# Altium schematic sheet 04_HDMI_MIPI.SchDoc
size A2; ApprovedBy: DNP; CheckedBy: DNP; Author: DNP; CompanyName: Google LLC; DrawnBy: DNP; Engineer: Bangfei/Michael/Leo; Organization: Google LLC; Address1: 1600 Amphitheatre Parkway; Address2: Mountain View, CA 94043; Address3: DNP; Address4: DNP; DocumentNumber: DNP; Revision: PVT; SheetNumber: 4; SheetTotal: 11; VersionControl_RevNumber: DNP; IsUserConfigurable: DNP
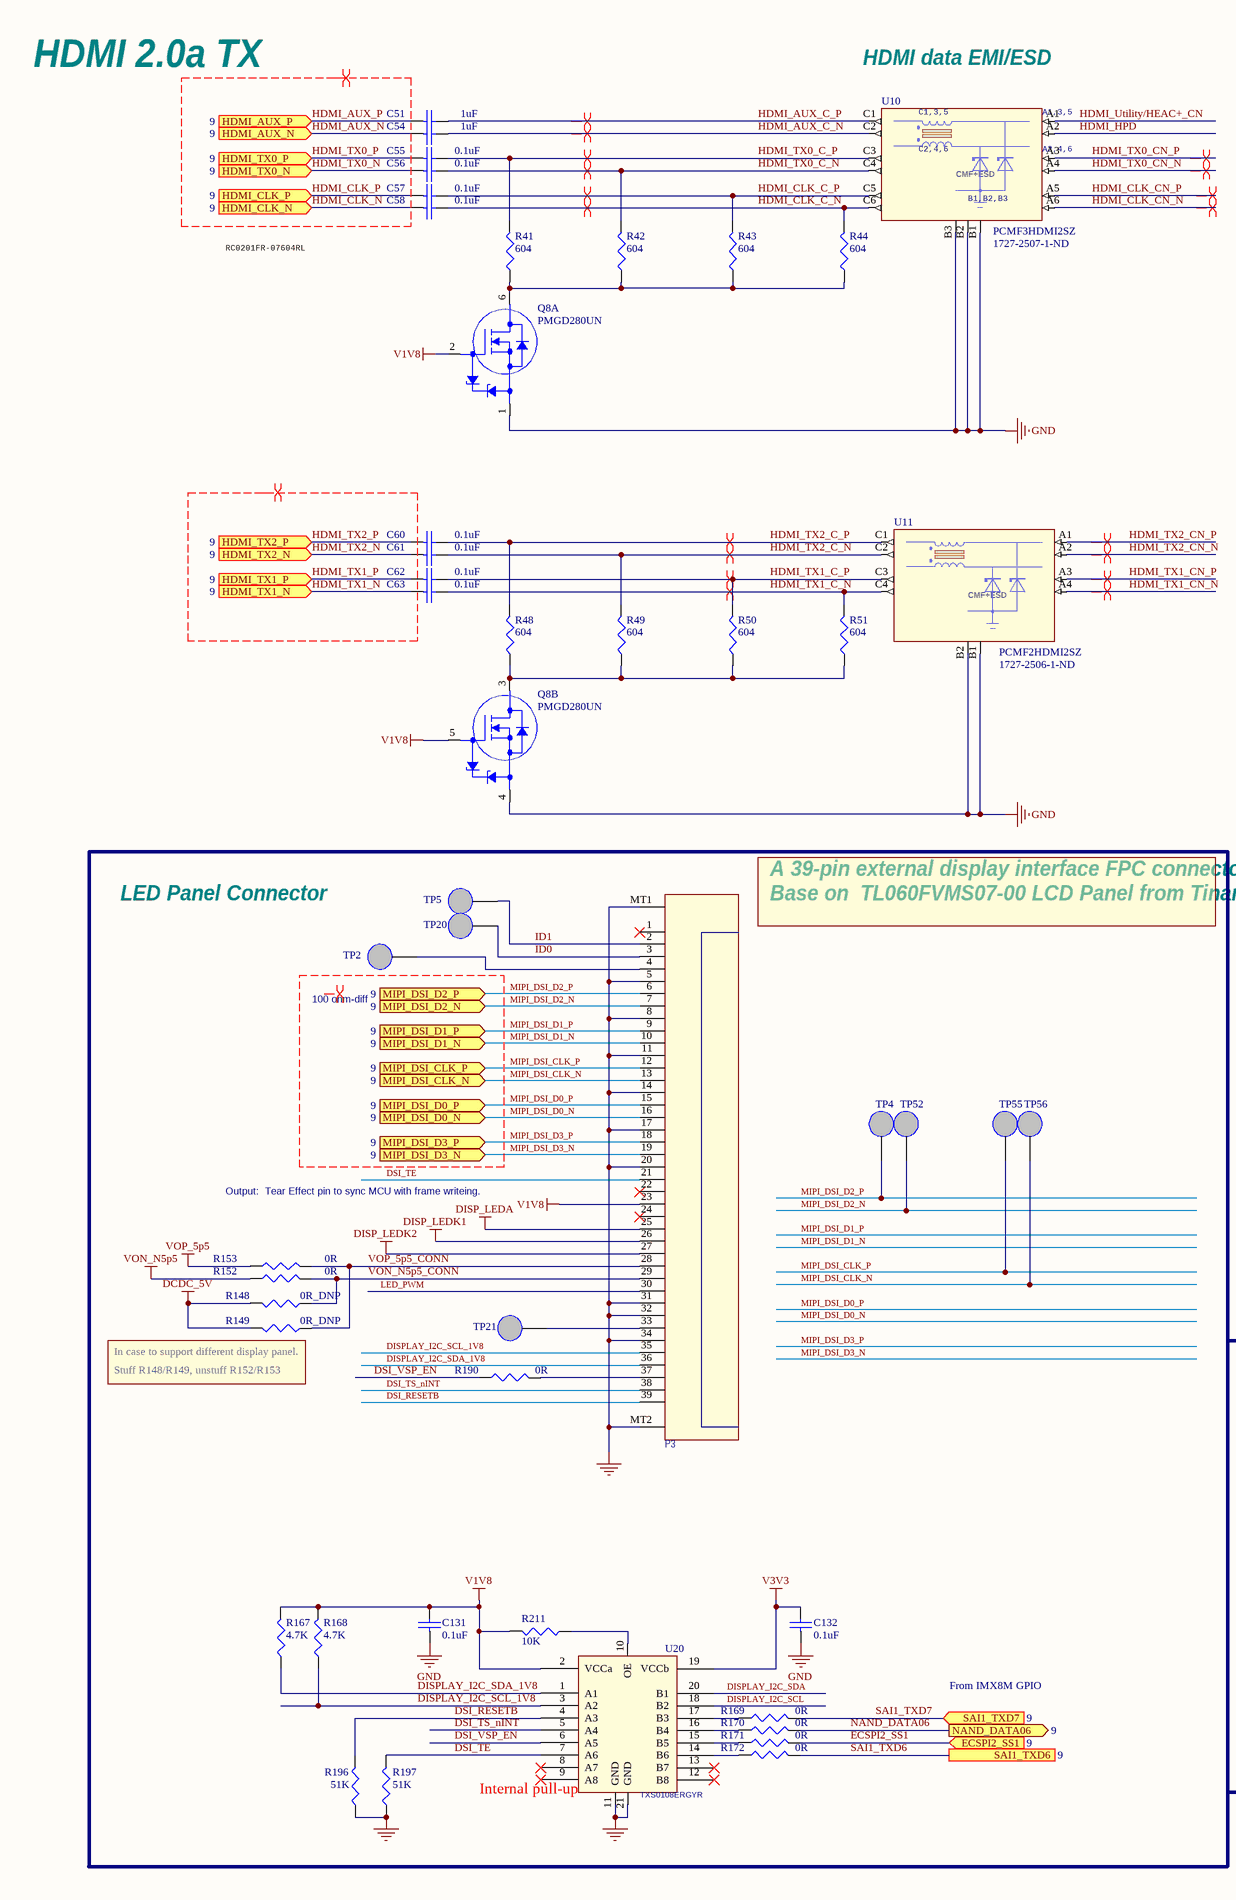
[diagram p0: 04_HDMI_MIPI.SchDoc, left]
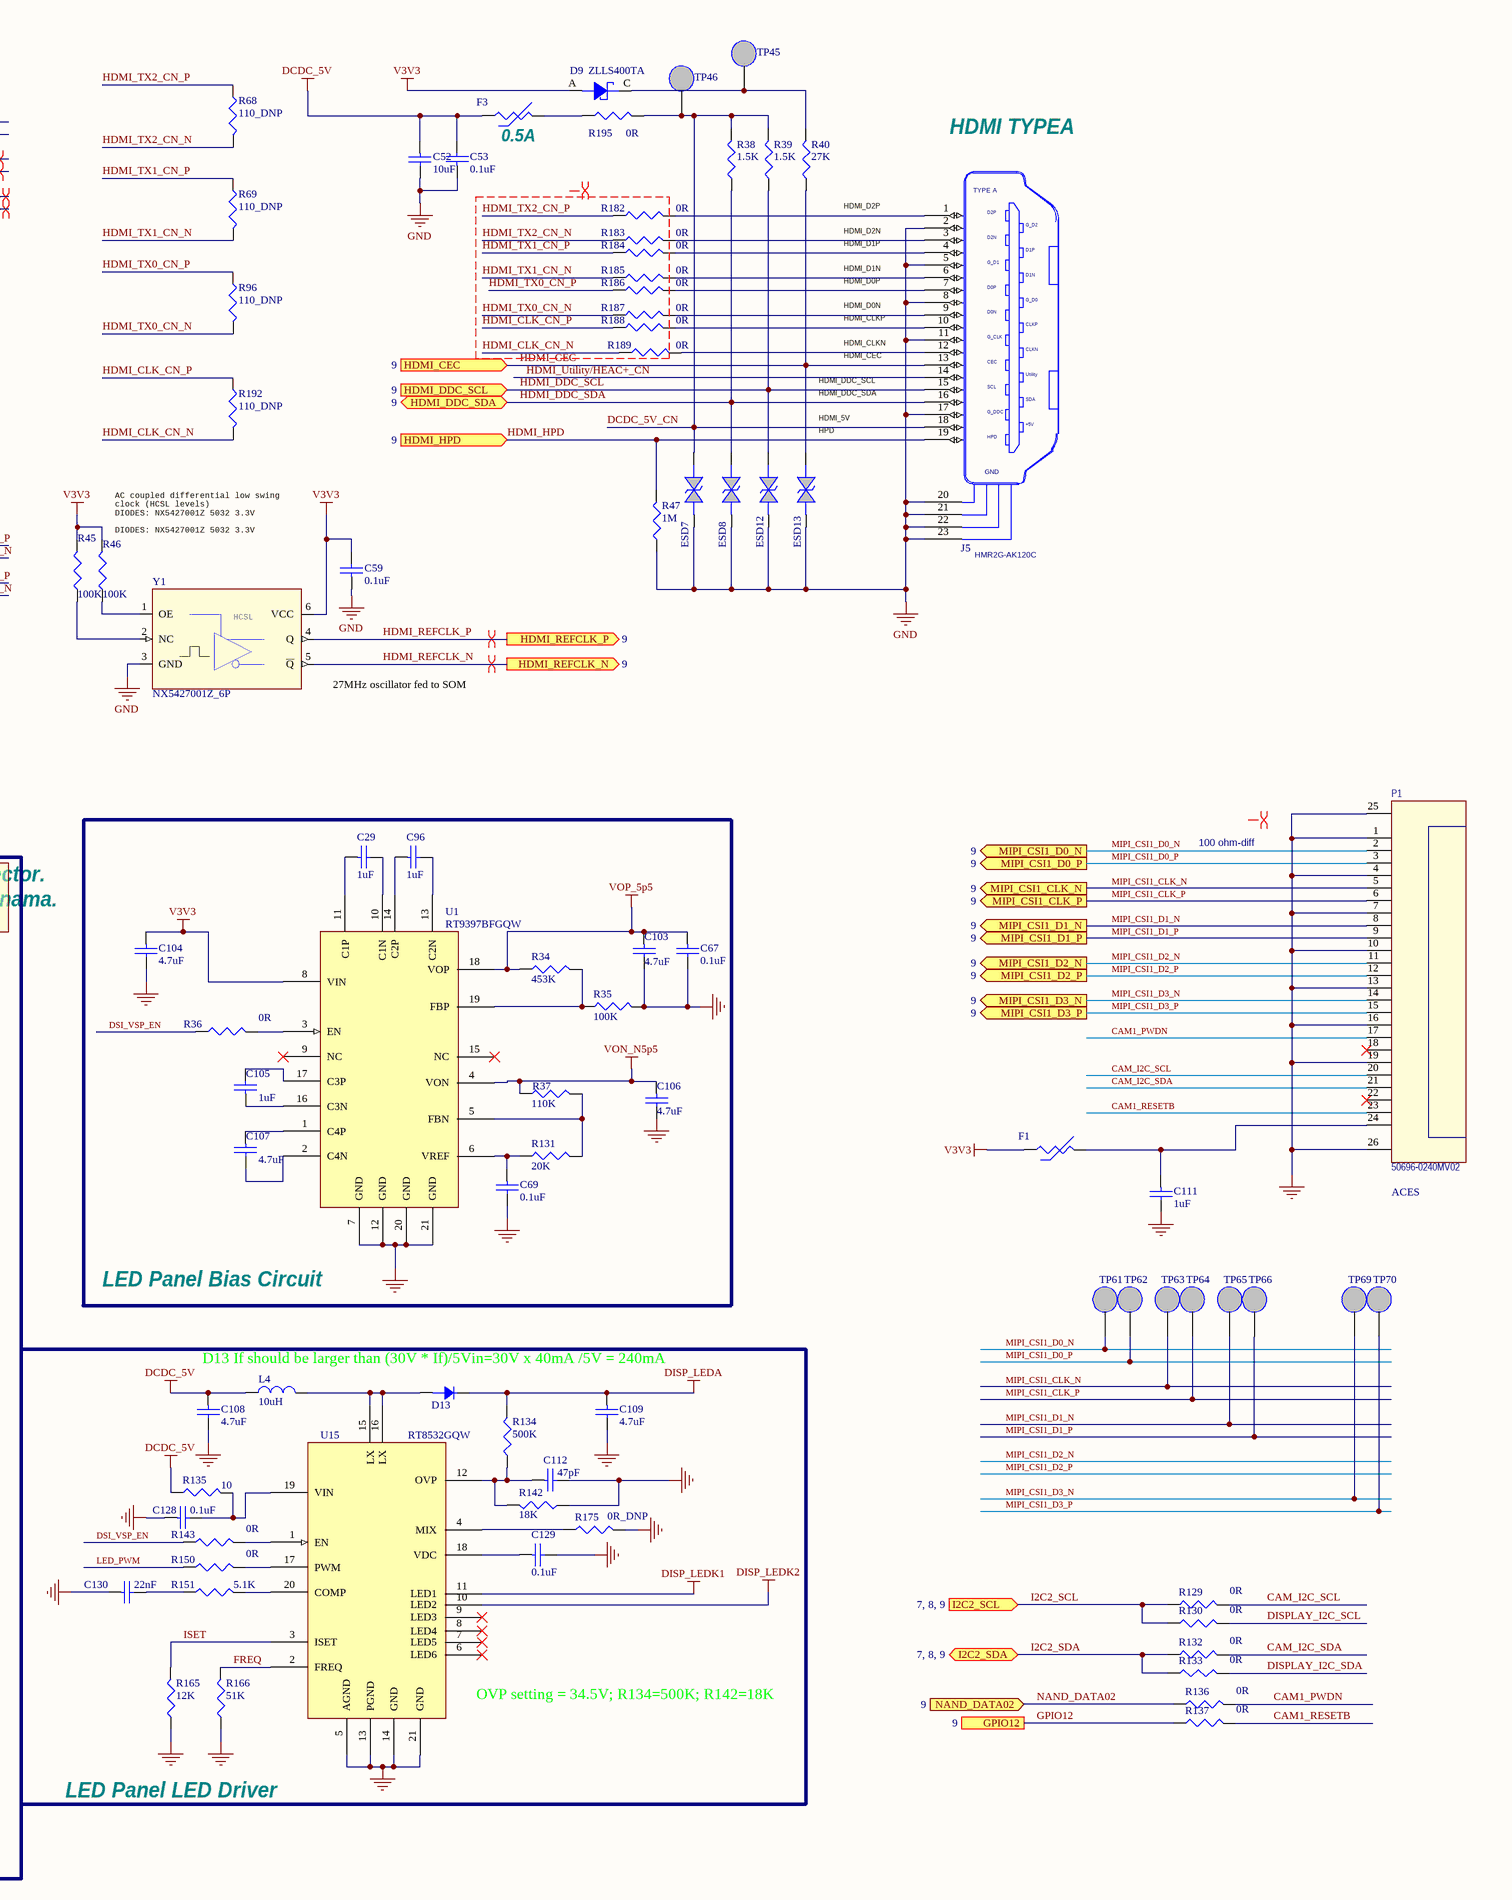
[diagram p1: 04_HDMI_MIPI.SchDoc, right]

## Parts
C29  value 1uF  [0201]  (hidden comment: 1uF/6.3V)
C51  value 1uF  [0402]  (hidden comment: 1uF/25V)
C52  value 10uF  [0402]  (hidden comment: 10uF/10V)
C53  value 0.1uF  [0201]  (hidden comment: 0.1uF/10V)
C54  value 1uF  [0402]  (hidden comment: 1uF/25V)
C55  value 0.1uF  [0201]  (hidden comment: 0.1uF/10V)
C56  value 0.1uF  [0201]  (hidden comment: 0.1uF/10V)
C57  value 0.1uF  [0201]  (hidden comment: 0.1uF/10V)
C58  value 0.1uF  [0201]  (hidden comment: 0.1uF/10V)
C59  value 0.1uF  [0201]  (hidden comment: 0.1uF/10V)
C60  value 0.1uF  [0201]  (hidden comment: 0.1uF/10V)
C61  value 0.1uF  [0201]  (hidden comment: 0.1uF/10V)
C62  value 0.1uF  [0201]  (hidden comment: 0.1uF/10V)
C63  value 0.1uF  [0201]  (hidden comment: 0.1uF/10V)
C67  value 0.1uF  [0201]  (hidden comment: 0.1uF/10V)
C69  value 0.1uF  [0201]  (hidden comment: 0.1uF/10V)
C96  value 1uF  [0201]  (hidden comment: 1uF/6.3V)
C103  value 4.7uF  [0402]  (hidden comment: 4.7uF/10V)
C104  value 4.7uF  [0402]  (hidden comment: 4.7uF/10V)
C105  value 1uF  [0201]  (hidden comment: 1uF/6.3V)
C106  value 4.7uF  [0402]  (hidden comment: 4.7uF/10V)
C107  value 4.7uF  [0402]  (hidden comment: 4.7uF/10V)
C108  value 4.7uF  [0402]  (hidden comment: 4.7uF/10V)
C109  value 4.7uF  [0402]  (hidden comment: 4.7uF/10V)
C111  value 1uF  [0201]  (hidden comment: 1uF/6.3V)
C112  value 47pF  [0201]  (hidden comment: 47pF/25V)
C128  value 0.1uF  [0201]  (hidden comment: 0.1uF/10V)
C129  value 0.1uF  [0201]  (hidden comment: 0.1uF/10V)
C130  value 22nF  [0201]  (hidden comment: 22nF/6.3V)
C131  value 0.1uF  [0201]  (hidden comment: 0.1uF/10V)
C132  value 0.1uF  [0201]  (hidden comment: 0.1uF/10V)
D9  ZLLS400TA  [SOD323]
D13  CUS10F30  [0805-Diode]  (value not drawn)
ESD7  3.5pF/5V  [0201]  (value not drawn)
ESD8  3.5pF/5V  [0201]  (value not drawn)
ESD12  3.5pF/5V  [0201]  (value not drawn)
ESD13  3.5pF/5V  [0201]  (value not drawn)
F1  PTC_FUSE_0805_0p5A  [0805]  (value not drawn)
F3  PTC_FUSE_0805_0p5A  [0805]  (value not drawn)
J5  HMR2G-AK120C  [HDMI19-HMR2G-AK120C]
L4  10uH  [AP3-00115]
P1  50696-0240MV02  QCI Supplier: ACES  [FPC24-0_5-14_18x4_71MM]
P3  FH26-39S-0.3SHW(05)  [FPC39-FH26W-39S-0_3SHW]  (value not drawn)
Q8  PMGD280UN  [SOT-363_0P65_SMT]  (parts A,B of 2)
R34  453K  [0201]
R35  100K  [0201]
R36  0R  [0201]
R37  110K  [0201]
R38  1.5K  [0201]
R39  1.5K  [0201]
R40  27K  [0201]
R41  604  [0201]
R42  604  [0201]
R43  604  [0201]
R44  604  [0201]
R45  100K  [0201]
R46  100K  [0201]
R47  1M  [0201]
R48  604  [0201]
R49  604  [0201]
R50  604  [0201]
R51  604  [0201]
R68  value 110_DNP  [0201]  (hidden comment: 110)
R69  value 110_DNP  [0201]  (hidden comment: 110)
R96  value 110_DNP  [0201]  (hidden comment: 110)
R129  0R  [0201]
R130  0R  [0201]
R131  20K  [0201]
R132  0R  [0201]
R133  0R  [0201]
R134  500K  [0201]
R135  10  [0201]
R136  0R  [0201]
R137  0R  [0201]
R142  18K  [0201]
R143  0R  [0201]
R148  0R_DNP  [0603]
R149  0R_DNP  [0603]
R150  0R  [0201]
R151  5.1K  [0201]
R152  0R  [0603]
R153  0R  [0603]
R165  12K  [0402]
R166  51K  [0201]
R167  4.7K  [0402]
R168  4.7K  [0402]
R169  0R  [0201]
R170  0R  [0201]
R171  0R  [0201]
R172  0R  [0201]
R175  0R_DNP  [0201]
R182  0R  [0201]
R183  0R  [0201]
R184  0R  [0201]
R185  0R  [0201]
R186  0R  [0201]
R187  0R  [0201]
R188  0R  [0201]
R189  0R  [0201]
R190  value 0R  [0201]  (hidden comment: 0R_DNP)
R192  value 110_DNP  [0201]  (hidden comment: 110)
R195  0R  [0603]
R196  51K  [0201]
R197  51K  [0201]
R211  10K  [0201]
TP2  TP NM  [TP_SMD]  (value not drawn)  (no BOM)
TP4  TP NM  [TP2040]  (value not drawn)  (no BOM)
TP5  TP NM  [TP_SMD]  (value not drawn)  (no BOM)
TP20  TP NM  [TP_SMD]  (value not drawn)  (no BOM)
TP21  TP NM  [TP_SMD]  (value not drawn)  (no BOM)
TP45  TP NM  [TP_SMD_L]  (value not drawn)  (no BOM)
TP46  TP NM  [TP_SMD_L]  (value not drawn)  (no BOM)
TP52  TP NM  [TP2040]  (value not drawn)  (no BOM)
TP55  TP NM  [TP2040]  (value not drawn)  (no BOM)
TP56  TP NM  [TP2040]  (value not drawn)  (no BOM)
TP61  TP NM  [TP2040]  (value not drawn)  (no BOM)
TP62  TP NM  [TP2040]  (value not drawn)  (no BOM)
TP63  TP NM  [TP2040]  (value not drawn)  (no BOM)
TP64  TP NM  [TP2040]  (value not drawn)  (no BOM)
TP65  TP NM  [TP2040]  (value not drawn)  (no BOM)
TP66  TP NM  [TP2040]  (value not drawn)  (no BOM)
TP69  TP NM  [TP2040]  (value not drawn)  (no BOM)
TP70  TP NM  [TP2040]  (value not drawn)  (no BOM)
U1  RT9397BFGQW  [WQFN20-0_4-3_1x3_1-H0_8MM-1]
U10  PCMF3HDMI2SZ  Supplier Part Number 1: 1727-2507-1-ND  [WLCSP15_0P4_2P42X1P22_SMDP]
U11  PCMF2HDMI2SZ  Supplier Part Number 1: 1727-2506-1-ND  [WLCSP10_0P4_1P2X1P6MM_SMDP]
U15  RT8532GQW  [WQFN20-0_4-3_1x3_1-H0_8MM-2]
U20  TXS0108ERGYR  [VQFN20-0_5-4_65X3_65MM-H1MM]
Y1  NX5427001Z_6P  [OSC6_1P27_5P2X3P4]

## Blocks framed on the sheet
LED Panel Bias Circuit: C29 C67 C69 C96 C103-C107 R34-R37 R131 U1
LED Panel LED Driver: C108 C109 C112 C128-C130 D13 L4 R134 R135 R142 R143 R150 R151 R165 R166 R175 U15

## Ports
ECSPI2_SS1 (in, see 9), GPIO12 (see 9), HDMI_AUX_N (in, see 9), HDMI_AUX_P (in, see 9), HDMI_CEC (in, see 9), HDMI_CLK_N (in, see 9), HDMI_CLK_P (in, see 9), HDMI_DDC_SCL (in, see 9), HDMI_DDC_SDA (bidir, see 9), HDMI_HPD (in, see 9), HDMI_REFCLK_N (out, see 9), HDMI_REFCLK_P (out, see 9), HDMI_TX0_N (in, see 9), HDMI_TX0_P (in, see 9), HDMI_TX1_N (in, see 9), HDMI_TX1_P (in, see 9), HDMI_TX2_N (in, see 9), HDMI_TX2_P (in, see 9), I2C2_SCL (in, see 7, 8, 9), I2C2_SDA (bidir, see 7, 8, 9), MIPI_CSI1_CLK_N (out, see 9), MIPI_CSI1_CLK_P (out, see 9), MIPI_CSI1_D0_N (out, see 9), MIPI_CSI1_D0_P (out, see 9), MIPI_CSI1_D1_N (out, see 9), MIPI_CSI1_D1_P (out, see 9), MIPI_CSI1_D2_N (out, see 9), MIPI_CSI1_D2_P (out, see 9), MIPI_CSI1_D3_N (out, see 9), MIPI_CSI1_D3_P (out, see 9), MIPI_DSI_CLK_N (in, see 9), MIPI_DSI_CLK_P (in, see 9), MIPI_DSI_D0_N (in, see 9), MIPI_DSI_D0_P (in, see 9), MIPI_DSI_D1_N (in, see 9), MIPI_DSI_D1_P (in, see 9), MIPI_DSI_D2_N (in, see 9), MIPI_DSI_D2_P (in, see 9), MIPI_DSI_D3_N (in, see 9), MIPI_DSI_D3_P (in, see 9), NAND_DATA02 (in, see 9), NAND_DATA06 (out, see 9), SAI1_TXD6 (see 9), SAI1_TXD7 (in, see 9)

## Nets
DCDC_5V: C52.1 C53.2 C108.1 F3.1 L4.1 R135.1 R148.2 R149.2
DISP_LEDA: C109.1 D13.K P3.25 R134.2
DISP_LEDK1: P3.26 U15.11(LED1)
DISP_LEDK2: P3.27 U15.10(LED2)
GND: C52.2 C53.1 C59.1 C67.2 C69.2 C103.2 C104.2 C106.2 C108.2 C109.2 C111.2 C112.2 C128.1 C129.2 C130.1 C131.1 C132.1 ESD7.1 ESD8.1 ESD12.1 ESD13.1 J5.2(D2GND) J5.5(D1GND) J5.8(D0GND) J5.11(CKGND) J5.17(DDCGND) J5.20(GND1) J5.21(GND2) J5.22(GND3) J5.23(GND4) P1.1 P1.4 P1.7 P1.10 P1.13 P1.16 P1.19 P1.25 P1.26 P3.5 P3.8 P3.11 P3.14 P3.17 P3.20 P3.31 P3.32 P3.34 P3.MT1 P3.MT2 Q8.1(S1) Q8.4(S2) R35.2 R47.1 R142.1 R165.1 R166.1 R175.2 R196.1 R197.1 U1.7(GND) U1.12(GND) U1.20(GND) U1.21(GND) U10.B1(GND_CH1) U10.B2(GND_CH2) U10.B3(GND_CH3) U11.B1(GND_CH1) U11.B2(GND_CH2) U15.5(AGND) U15.13(PGND) U15.14(GND) U15.21(GND) U20.11(GND) U20.21(GND) Y1.3(GND)
V1V8: C131.2 P3.23 Q8.2(G1) Q8.5(G2) R167.2 R168.2 R211.2 U20.2(VCCa)
V3V3: C59.2 C104.1 C132.2 D9.A F1.1 R45.2 R46.2 U1.8(VIN) U20.19(VCCb) Y1.6(VCC)
VON_N5p5: C106.1 R37.1 R152.1 U1.4(VON)
VOP_5p5: C67.1 C103.1 R34.1 R153.1 U1.18(VOP)
CAM1_PWDN: P1.17 R136.2
CAM1_RESETB: P1.23 R137.2
CAM_I2C_SCL: P1.20 R129.2
CAM_I2C_SDA: P1.21 R132.2
DCDC_5V_CN: ESD7.2 J5.18(+5V) R38.2 R39.2 R195.2 TP46.1
DISPLAY_I2C_SCL: R130.2 U20.18(B2)
DISPLAY_I2C_SCL_1V8: P3.35 R168.1 U20.3(A2)
DISPLAY_I2C_SDA: R133.2 U20.20(B1)
DISPLAY_I2C_SDA_1V8: P3.36 R167.1 U20.1(A1)
DSI_RESETB: P3.39 R196.2 U20.4(A3)
DSI_TE: P3.21 R197.2 U20.7(A6)
DSI_TS_nINT: P3.38 U20.5(A4)
DSI_VSP_EN: R36.1 R143.1 R190.1 U20.6(A5)
ECSPI2_SS1: R171.2 ; port ECSPI2_SS1
FREQ: R166.2 U15.2(FREQ)
GPIO12: R137.1 ; port GPIO12
HDMI_AUX_C_N: C54.2 U10.C2(CH1_OUT-)
HDMI_AUX_C_P: C51.2 U10.C1(CH1_OUT+)
HDMI_AUX_N: C54.1 ; port HDMI_AUX_N
HDMI_AUX_P: C51.1 ; port HDMI_AUX_P
HDMI_CEC: ESD13.2 J5.13(CEC) R40.1 ; port HDMI_CEC
HDMI_CLK_C_N: C58.2 R44.2 U10.C6(CH3_OUT-)
HDMI_CLK_C_P: C57.2 R43.2 U10.C5(CH3_OUT+)
HDMI_CLK_CN_N: R189.1 R192.2 U10.A6(CH3_IN-)
HDMI_CLK_CN_P: R188.1 R192.1 U10.A5(CH3_IN+)
HDMI_CLK_N: C58.1 ; port HDMI_CLK_N
HDMI_CLK_P: C57.1 ; port HDMI_CLK_P
HDMI_DDC_SCL: ESD12.2 J5.15(SCL) R39.1 ; port HDMI_DDC_SCL
HDMI_DDC_SDA: ESD8.2 J5.16(SDA) R38.1 ; port HDMI_DDC_SDA
HDMI_HPD: J5.19(HPD) R47.2 U10.A2(CH1_IN-) ; port HDMI_HPD
HDMI_REFCLK_N: Y1.5(~{Q}) ; port HDMI_REFCLK_N
HDMI_REFCLK_P: Y1.4(Q) ; port HDMI_REFCLK_P
HDMI_TX0_C_N: C56.2 R42.2 U10.C4(CH2_OUT-)
HDMI_TX0_C_P: C55.2 R41.2 U10.C3(CH2_OUT+)
HDMI_TX0_CN_N: R96.2 R187.1 U10.A4(CH2_IN-)
HDMI_TX0_CN_P: R96.1 R186.1 U10.A3(CH2_IN+)
HDMI_TX0_N: C56.1 ; port HDMI_TX0_N
HDMI_TX0_P: C55.1 ; port HDMI_TX0_P
HDMI_TX1_C_N: C63.2 R51.2 U11.C4(CH2_OUT-)
HDMI_TX1_C_P: C62.2 R50.2 U11.C3(CH2_OUT+)
HDMI_TX1_CN_N: R69.2 R185.1 U11.A4(CH2_IN-)
HDMI_TX1_CN_P: R69.1 R184.1 U11.A3(CH2_IN+)
HDMI_TX1_N: C63.1 ; port HDMI_TX1_N
HDMI_TX1_P: C62.1 ; port HDMI_TX1_P
HDMI_TX2_C_N: C61.2 R49.2 U11.C2(CH1_OUT-)
HDMI_TX2_C_P: C60.2 R48.2 U11.C1(CH1_OUT+)
HDMI_TX2_CN_N: R68.2 R183.1 U11.A2(CH1_IN-)
HDMI_TX2_CN_P: R68.1 R182.1 U11.A1(CH1_IN+)
HDMI_TX2_N: C61.1 ; port HDMI_TX2_N
HDMI_TX2_P: C60.1 ; port HDMI_TX2_P
HDMI_Utility/HEAC+_CN: J5.14(Utility) U10.A1(CH1_IN+)
I2C2_SCL: R129.1 R130.1 ; port I2C2_SCL
I2C2_SDA: R132.1 R133.1 ; port I2C2_SDA
ID0: P3.3 TP20.1
ID1: P3.2 TP5.1
ISET: R165.2 U15.3(ISET)
LED_PWM: P3.30 R150.1
MIPI_CSI1_CLK_N: P1.5 TP63.1 ; port MIPI_CSI1_CLK_N
MIPI_CSI1_CLK_P: P1.6 TP64.1 ; port MIPI_CSI1_CLK_P
MIPI_CSI1_D0_N: P1.2 TP61.1 ; port MIPI_CSI1_D0_N
MIPI_CSI1_D0_P: P1.3 TP62.1 ; port MIPI_CSI1_D0_P
MIPI_CSI1_D1_N: P1.8 TP65.1 ; port MIPI_CSI1_D1_N
MIPI_CSI1_D1_P: P1.9 TP66.1 ; port MIPI_CSI1_D1_P
MIPI_CSI1_D2_N: P1.11 ; port MIPI_CSI1_D2_N
MIPI_CSI1_D2_P: P1.12 ; port MIPI_CSI1_D2_P
MIPI_CSI1_D3_N: P1.14 TP69.1 ; port MIPI_CSI1_D3_N
MIPI_CSI1_D3_P: P1.15 TP70.1 ; port MIPI_CSI1_D3_P
MIPI_DSI_CLK_N: P3.13 TP56.1 ; port MIPI_DSI_CLK_N
MIPI_DSI_CLK_P: P3.12 TP55.1 ; port MIPI_DSI_CLK_P
MIPI_DSI_D0_N: P3.16 ; port MIPI_DSI_D0_N
MIPI_DSI_D0_P: P3.15 ; port MIPI_DSI_D0_P
MIPI_DSI_D1_N: P3.10 ; port MIPI_DSI_D1_N
MIPI_DSI_D1_P: P3.9 ; port MIPI_DSI_D1_P
MIPI_DSI_D2_N: P3.7 TP52.1 ; port MIPI_DSI_D2_N
MIPI_DSI_D2_P: P3.6 TP4.1 ; port MIPI_DSI_D2_P
MIPI_DSI_D3_N: P3.19 ; port MIPI_DSI_D3_N
MIPI_DSI_D3_P: P3.18 ; port MIPI_DSI_D3_P
NAND_DATA02: R136.1 ; port NAND_DATA02
NAND_DATA06: R170.2 ; port NAND_DATA06
SAI1_TXD6: R172.2 ; port SAI1_TXD6
SAI1_TXD7: R169.2 ; port SAI1_TXD7
VON_N5p5_CONN: P3.29 R148.1 R152.2
VOP_5p5_CONN: P3.28 R149.1 R153.2
NetC29_1: C29.1 U1.11(C1P)
NetC29_2: C29.2 U1.10(C1N)
NetC69_1: C69.1 R131.1 U1.6(VREF)
NetC96_1: C96.1 U1.14(C2P)
NetC96_2: C96.2 U1.13(C2N)
NetC105_1: C105.1 U1.16(C3N)
NetC105_2: C105.2 U1.17(C3P)
NetC107_1: C107.1 U1.1(C4P)
NetC107_2: C107.2 U1.2(C4N)
NetC111_1: C111.1 F1.2 P1.24
NetC112_1: C112.1 R134.1 R142.2 U15.12(OVP)
NetC128_2: C128.2 R135.2 U15.19(VIN)
NetC129_1: C129.1 U15.18(VDC)
NetC130_2: C130.2 R151.1
NetD9_C: D9.C R40.2 TP45.1
NetD13_A: D13.A L4.2 U15.15(LX) U15.16(LX)
NetF3_2: F3.2 R195.1
NetJ5_1: J5.1(D2+) R182.2
NetJ5_3: J5.3(D2-) R183.2
NetJ5_4: J5.4(D1+) R184.2
NetJ5_6: J5.6(D1-) R185.2
NetJ5_7: J5.7(D0+) R186.2
NetJ5_9: J5.9(D0-) R187.2
NetJ5_10: J5.10(CK+) R188.2
NetJ5_12: J5.12(CK-) R189.2
NetP3_4: P3.4 TP2.1
NetP3_33: P3.33 TP21.1
NetP3_37: P3.37 R190.2
NetQ8_3: Q8.3(D2) R48.1 R49.1 R50.1 R51.1
NetQ8_6: Q8.6(D1) R41.1 R42.1 R43.1 R44.1
NetR34_2: R34.2 R35.1 U1.19(FBP)
NetR36_2: R36.2 U1.3(EN)
NetR37_2: R37.2 R131.2 U1.5(FBN)
NetR45_1: R45.1 Y1.2(NC)
NetR46_1: R46.1 Y1.1(OE)
NetR143_2: R143.2 U15.1(EN)
NetR150_2: R150.2 U15.17(PWM)
NetR151_2: R151.2 U15.20(COMP)
NetR169_1: R169.1 U20.17(B3)
NetR170_1: R170.1 U20.16(B4)
NetR171_1: R171.1 U20.15(B5)
NetR172_1: R172.1 U20.14(B6)
NetR175_1: R175.1 U15.4(MIX)
NetR211_1: R211.1 U20.10(OE)

Not connected (* = marked no-connect by the designer): P1 18* 22*; P3 1* 22* 24*; U1 9(NC)* 15(NC)*; U15 6(LED6)* 7(LED5)* 8(LED4)* 9(LED3)*; U20 8(A7)* 9(A8)* 12(B8)* 13(B7)*

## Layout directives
differential pair: (no net found under the mark), HDMI_AUX_C_N, HDMI_AUX_C_P, HDMI_AUX_N, HDMI_AUX_P, HDMI_CLK_C_N, HDMI_CLK_C_P, HDMI_CLK_CN_N, HDMI_CLK_CN_P, HDMI_CLK_N, HDMI_CLK_P, HDMI_REFCLK_N, HDMI_REFCLK_P, HDMI_TX0_C_N, HDMI_TX0_C_P, HDMI_TX0_CN_N, HDMI_TX0_CN_P, HDMI_TX0_N, HDMI_TX0_P, HDMI_TX1_C_N, HDMI_TX1_C_P, HDMI_TX1_CN_N, HDMI_TX1_CN_P, HDMI_TX1_N, HDMI_TX1_P, HDMI_TX2_C_N, HDMI_TX2_C_P, HDMI_TX2_CN_N, HDMI_TX2_CN_P, HDMI_TX2_N, HDMI_TX2_P

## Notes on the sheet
- HDMI 2.0a TX
- HDMI data EMI/ESD
- (near F3) 0.5A
- HDMI TYPEA
- (near R40) HDMI_D2P
- HDMI_D2N
- RC0201FR-07604RL
- HDMI_D1P
- HDMI_D1N
- HDMI_D0P
- HDMI_D0N
- HDMI_CLKP
- HDMI_CLKN
- HDMI_CEC
- HDMI_DDC_SCL
- HDMI_DDC_SDA
- HDMI_5V
- (near ESD13) HPD
- (near R46) DIODES: NX5427001Z 5032 3.3V
- AC coupled differential low swing
  clock (HCSL levels)
  DIODES: NX5427001Z 5032 3.3V
- (near Y1) 27MHz oscillator fed to SOM
- 100 ohm-diff
- LED Panel Connector
- A 39-pin external display interface FPC connector.
- Base on  TL060FVMS07-00 LCD Panel from Tinama.
- (near TP2) 100 ohm-diff
- Output:  Tear Effect pin to sync MCU with frame writeing.
- (near R149) In case to support different display panel.
- (near R149) Stuff R148/R149, unstuff R152/R153
- D13 If should be larger than (30V * If)/5Vin=30V x 40mA /5V = 240mA
- From IMX8M GPIO
- (near U15) OVP setting = 34.5V; R134=500K; R142=18K
- (near U20) Internal pull-up

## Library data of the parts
C29 C96 C105 = CAP_0201_1.0uF: CAP CER 1UF 6.3V 20% X5R 0201; MPN: C0603X5R0J105M030BC; QCI MPN: GRM033R60J105M; QPN: CH5101M9E02; QPN Description: CAP CHIP 1UF 6.3V(+-20%,X5R,0201); Function Code: LCD
C51 C54 = CAP_0402_1.0uF_25V: CAP CER 1.0UF 25V 10% X5R 0402; MPN: TMK105BJ105MV-F; QCI MPN: GRM155R61E105K; QPN: CH5104K9B01; QPN Description: CAP CHIP 1UF 25V(+-10%,X5R,0402); Function Code: HMI
C52 = CAP_0402_10uF: CAP CER 10UF 10V 20% X5R 0402; MPN: CL05A106MP5NUNC; QCI MPN: GRM155R61A106M; QPN: CH6102M9B00; QPN Description: CAP CHIP 10U 10V (+-20%, X5R, 0402)'; Function Code: HMI
C53 C55-C58 C60-C63 = CAP_0201_0.1uF: CAP CER 0.1UF 10V 10% X5R 0201; MPN: C0603X5R1A104K030BC; QCI MPN: GRM033R61A104K; QPN: CH4102K9E00; QPN Description: CAP CHIP 0.1U 10V(+-10%,X5R,0201); Function Code: HMI
C59 = CAP_0201_0.1uF: CAP CER 0.1UF 10V 10% X5R 0201; MPN: C0603X5R1A104K030BC; QCI MPN: GRM033R61A104K; QPN: CH4102K9E00; QPN Description: CAP CHIP 0.1U 10V(+-10%,X5R,0201); Function Code: SOC
C67 C69 C128 C129 C131 C132 = CAP_0201_0.1uF: CAP CER 0.1UF 10V 10% X5R 0201; MPN: C0603X5R1A104K030BC; QCI MPN: GRM033R61A104K; QPN: CH4102K9E00; QPN Description: CAP CHIP 0.1U 10V(+-10%,X5R,0201); Function Code: LCD
C103 C104 C106-C109 = CAP_0402_4.7uF: CAP CER 4.7UF 10V 20% X5R 0402; MPN: C1005X5R1A475M050BC; QCI MPN: GRM155R61A475M; QPN: CH5472M9B01; QPN Description: CAP CHIP 4.7U 10V(+-20%,X5R,0402); Function Code: LCD
C111 = CAP_0201_1.0uF: CAP CER 1UF 6.3V 20% X5R 0201; MPN: C0603X5R0J105M030BC; QCI MPN: GRM033R60J105M; QPN: CH5101M9E02; QPN Description: CAP CHIP 1UF 6.3V(+-20%,X5R,0201); Function Code: CAM
C112 = CAP_0201_47pF: CAP CER 47PF 25V 0201; MPN: GRM0335C1E470FA01D; QCI MPN: GRM0335C1E470J; QPN: CH0474J0E09; QPN Description: CAP CHIP 47P 25V(+-5%,COG,0201); Function Code: LCD
C130 = CAP_0201_22nF: CAP CER 0.022UF 6.3V 10% X5R 0201; MPN: CC0201KRX5R5BB223; QCI MPN: GRM033R60J223K; QPN: CH3221K9E00; QPN Description: CAP CHIP 0.022U 6.3V(+-10%,X5R,0201); Function Code: LCD
D9 = DIODE_SCHTKY: DIODE SCHOTTKY 40V 520MA SOD323; Function Code: HMI; QPN: BCS400TA000; QPN Description: DIODE SCHOTTKY ZLLS400TA(20V,1A)
D13 = Diode_Schottky_0805: DIODE SCHOTTKY 20V 1A 0805; Function Code: LCD; QPN: BC0CUS10000; QPN Description: DIODE SMD SCHOTTKY  CUS10F30(30V,1A)
ESD7 ESD8 ESD12 ESD13 = DIODE BI-DIR TRIG: DIODE TVS 15kV 10V 50A 8pF SMT RoHS; MPN: DESD5V0V1BCSP-7; QPN: BC5V0V1BZ02; QPN Description: DIODE ESD SMD DESD5V0V1BCSP-7 6V,DSN0603; Function Code: HMI
F1 = PTC_FUSE_0805_0p5A: PTC FUSE 0.5A 0805; QCI MPN: SMD0805P050TF; QPN: DK050TPU004; QPN Description: FUSE SMD 0.5A 6V POLY(SMD0805P050TF); Function Code: CAM
F3 = PTC_FUSE_0805_0p5A: PTC FUSE 0.5A 0805; QCI MPN: SMD0805P050TF; QPN: DK050TPU004; QPN Description: FUSE SMD 0.5A 6V POLY(SMD0805P050TF); Function Code: HMI
J5 = CONN_HDMI_TYPEA_ACON_HMR2G-AK120C: CONN RCPT 19POS HDMI DIP WO FLANGE; Function Code: HMI; QPN: DFHD19MR637; QPN Description: CONN DIP HDMI 19P 2R MR(P0.5,H5.55)
L4 = INDUCTOR_LQH3NPN100MJ0: FIXED IND 10UH 710MA 300 MOHM; MPN: LQH3NPN100MJRL; Function Code: LCD; QPN: CV01009MN01; QPN Description: IND CHIP 10UH 0.81A +-20% LQH3NPN100MJRL
P1 = CONN_ACES_50696-0240MV02: Connector,FP, .5mm pitch, 24-pin, R/A,  SMT; QCI MPN: 50696-0240M-V02; Function Code: CAM; QPN: DFFC24FR095; QPN Description: CONN SMD FPC 24P 1R FR(P0.5,H1.0)
P3 = CONN_FH26-39S-0.3SHW(0.5): Connector,FP, .30mm pitch, 39-pin, R/A,  SMT; QPN: DFFC39FR004; QPN Description: CONN SMD FPC 39P 2R FR(P0.6,H0.1); Function Code: LCD
Q8 = TRAN_DUAL_NMOS_BSS138: TRANS MOSFET (20V,0.87A,0.4W) SOT363; QPN: BC5V0V1BZ02; QPN Description: DIODE ESD SMD DESD5V0V1BCSP-7 6V,DSN0603; Function Code: HMI
R34 = R_0201_453K: RES SMD 453K OHM JUMPER 1/20W  0201; MPN: ERJ-1GEF4533C; QCI MPN: RM02FTN4533; QPN: CS44531FE00; QPN Description: RES CHIP 453K 1/20W +-1%(0201); Function Code: LCD
R35 = R_0201_100K: RES SMD 100K OHM JUMPER 1/20W  0201; MPN: ERJ-1GEF1003C; QCI MPN: RC0201FR-07100KL; QPN: TS41001FE04; QPN Description: RES CHIP 100K 1/20W +-1%(0201)EMS-SEL; Function Code: LCD
R36 R143 R150 R169-R172 = R_0201_0: RES SMD 0.0OHM JUMPER 1/20W 0201; MPN: ERJ-1GN0R00C; QCI MPN: RC0201JR-130RL; QPN: CS00001JE18; QPN Description: RES CHIP 0(1/20W,+-5%,0201); Function Code: LCD
R37 = R_0201_110K: RES SMD 110K OHM  +/-1% 1/20W  0201; MPN: ERJ-1GNF1103C; QCI MPN: RC0201FR-07110KL; QPN: CS41101FE00; QPN Description: RES CHIP 110K 1/20W 1% (0201); Function Code: LCD
R38 R39 = R_0201_1.5K: RES SMD 1.5K OHM JUMPER 1/20W  0201; MPN: ERJ-1GEJ6152C; QCI MPN: RC0201FR-071K5L; QPN: CS21501FE01; QPN Description: RES CHIP 1.5K 1/20W +-1%(0201); Function Code: HMI
R40 = R_0201_27K: RES SMD 27K OHM JUMPER 1/20W  0201; MPN: ERJ-1GEF2702C; QCI MPN: RC0201JR-0727KL; QPN: CS32701JE00; QPN Description: RES CHIP 27K 1/20W +-5%(0201); Function Code: HMI
R41-R44 R48-R51 = R_0201_604: RES SMD 604 OHM JUMPER 1/20W  0201; MPN: ERJ-1GEF6040C; QCI MPN: RC0201FR-07604RL; QPN: CS16041FE01; QPN Description: RES CHIP 604 1/20W +-1%(0201); Function Code: HMI
R45 R46 = R_0201_100K: RES SMD 100K OHM JUMPER 1/20W  0201; MPN: ERJ-1GEF1003C; QCI MPN: RC0201FR-07100KL; QPN: TS41001FE04; QPN Description: RES CHIP 100K 1/20W +-1%(0201)EMS-SEL; Function Code: SOC
R47 = R_0201_1M: RES SMD 1M OHM 1% 1/20W 0201; MPN: ERJ-1GEF1004C; QCI MPN: RC0201FR-071ML; QPN: CS51001FE00; QPN Description: RES CHIP 1M 1/20W +-1%(0201); Function Code: HMI
R68 R69 R96 R192 = R_0201_110: RES SMD 110 OHM 1% 1/20W 0201; MPN: ERJ-1GEF1100C; QCI MPN: RC0201FR-07110RL; QPN: CS11101FE00; QPN Description: RES CHIP 110 1/20W +-1% (0201); Function Code: DBG
R129 R130 R132 R133 R136 R137 = R_0201_0: RES SMD 0.0OHM JUMPER 1/20W 0201; MPN: ERJ-1GN0R00C; QCI MPN: RC0201JR-130RL; QPN: CS00001JE18; QPN Description: RES CHIP 0(1/20W,+-5%,0201); Function Code: CAM
R131 = R_0201_20K: RES SMD 20K OHM 1% 1/20W 0201; MPN: ERJ-1GEF2002C; QCI MPN: RC0201FR-0720KL; QPN: CS32001FE00; QPN Description: RES CHIP 20K 1/20W +-1%(0201); Function Code: LCD
R134 = R_0201_499K: RES SMD 499K OHM JUMPER 1/20W  0201; MPN: ERJ-1GEF4993C; QCI MPN: RC0201FR-07499KL; QPN: CS44991FE00; QPN Description: RES CHIP 499K 1/20W +-1%(0201); Function Code: LCD
R135 = R_0201_10: RES SMD 10 OHM 1% 1/20W 0201; MPN: ERJ-1GEF10R0C; QCI MPN: RC0201JR-0710RL; QPN: CS01001JE11; QPN Description: RES CHIP 10(1/20W,+-5%,0201); Function Code: LCD
R142 = R_0201_24K: RES SMD 24K OHM 1% 1/20W 0201; MPN: ERJ-1GEF2402C; QCI MPN: RC0201FR-0724KL; QPN: CS31801FE02; QPN Description: RES CHIP 18K 1/20W +-1%(0201)SELASN; Function Code: LCD
R148 R149 = R_0603_0: RES SMD 0.0 OHM JUMPER 1/4W 0603; MPN: CRCW06030000Z0EAHP; QCI MPN: RC0603FR-070RL; DNP: V; QPN: CS00003F916; QPN Description: RES CHIP 0 1/10W +-1% (0603); Function Code: LCD
R151 = R_0201_5.1K: RES SMD 5.1K OHM JUMPER 1/20W  0201; MPN: ERJ-JGEF5101C; QCI MPN: RC0201FR-075K1L; QPN: CS25101FE00; QPN Description: RES CHIP 5.1K 1/20W +-1%(0201); Function Code: LCD
R152 R153 R195 = R_0603_0: RES SMD 0.0 OHM JUMPER 1/4W 0603; MPN: CRCW06030000Z0EAHP; QCI MPN: RC0603FR-070RL; QPN: CS00003F916; QPN Description: RES CHIP 0 1/10W +-1% (0603); Function Code: LCD
R165 = R_0402_12k: RES SMD 12K OHM 1% 1/10W 0402; MPN: ERJ-2RKF1202X; QCI MPN: RC0402JR-0712K; QPN: CS31202JB09; QPN Description: RES CHIP 12K 1/16W +-5% (0402); Function Code: LCD
R166 R196 R197 = R_0201_51K: RES SMD 51K OHM 1% 1/20W 0201; MPN: ERJ-1GEF5102C; QCI MPN: RC0201FR-0751KL; QPN Description: RES CHIP 51K(1/20W,+-1%,0201); Function Code: LCD; QPN: CS35101FE01
R167 R168 = R_0402_4.7k: RES SMD 4.7K OHM 1% 1/10W 0402; MPN: ERJ-2RKF4701X; QCI MPN: RC0402FR-074K7L; QPN: CS24702FB10; QPN Description: RES CHIP 4.7K 1/16W +-1%(0402); Function Code: LCD
R175 = R_0201_0: RES SMD 0.0OHM JUMPER 1/20W 0201; MPN: ERJ-1GN0R00C; QCI MPN: RC0201JR-130RL; DNP: V; QPN: CS00001JE18; QPN Description: RES CHIP 0(1/20W,+-5%,0201); Function Code: LCD
R182-R189 = R_0201_0: RES SMD 0.0OHM JUMPER 1/20W 0201; MPN: ERJ-1GN0R00C; QCI MPN: RC0201JR-130RL; QPN: CS00001JE18; QPN Description: RES CHIP 0(1/20W,+-5%,0201); Function Code: HMI
R190 = R_0201_0: RES SMD 0.0OHM JUMPER 1/20W 0201; MPN: ERJ-1GN0R00C; QCI MPN: RC0201JR-130RL; DNP: V; QPN: CS00001JE18; QPN Description: RES CHIP 0(1/20W,+-5%,0201); Function Code: USB
R211 = R_0201_10K: RES SMD 10K OHM JUMPER 1/20W  0201; MPN: ERJ-1GEF103C; QCI MPN: RC0201JR-1310KL; QPN: CS31001JE16; QPN Description: RES CHIP 10K 1/20W +-5%(0201); Function Code: DBG
TP2 TP5 TP20 TP21 = TP: TEST POIN
TP4 TP45 TP46 TP52 TP55 TP56 TP61-TP66 TP69 TP70 = TP_L: TEST POINT (Large)
U1 = RT9397BF: IC, Charge Pump Controller, WQFN20; Function Code: LCD; QPN: AL009397000; QPN Description: IC CTRL(20P)RT9397BFGQW(WQFN)
U10 = PCMF3HDMI2SZ: Function Code: HMI; QPN: CX3HDMI2000; QPN Description: EMI FILTER PCMF2HDMI3S(3,100NA)
U11 = PCMF2HDMI2SZ: Function Code: HMI; QPN: CX2HDMI2000; QPN Description: EMI FILTER PCMF2HDMI2S(2,100NA)
U15 = RT8532: IC, 6-string 43V White LED drivers with Boost Regulator, WQFN20; QPN: AL008532000; QPN Description: IC CTRL (20P) RT8532GQW (WQFN-20L 3X3); Function Code: LCD
U20 = TXS0108ERGYR: Voltage Level Translator Bidirectional 1 Circuit 8 Channel 60Mbps 20-VQFN (3.5x4.5); QPN: AL000108001; QPN Description: IC OTHER(20P) TXS0108ERGYR(QFN); Function Code: LCD
Y1 = NX5427001Z_6P: Function Code: SOC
